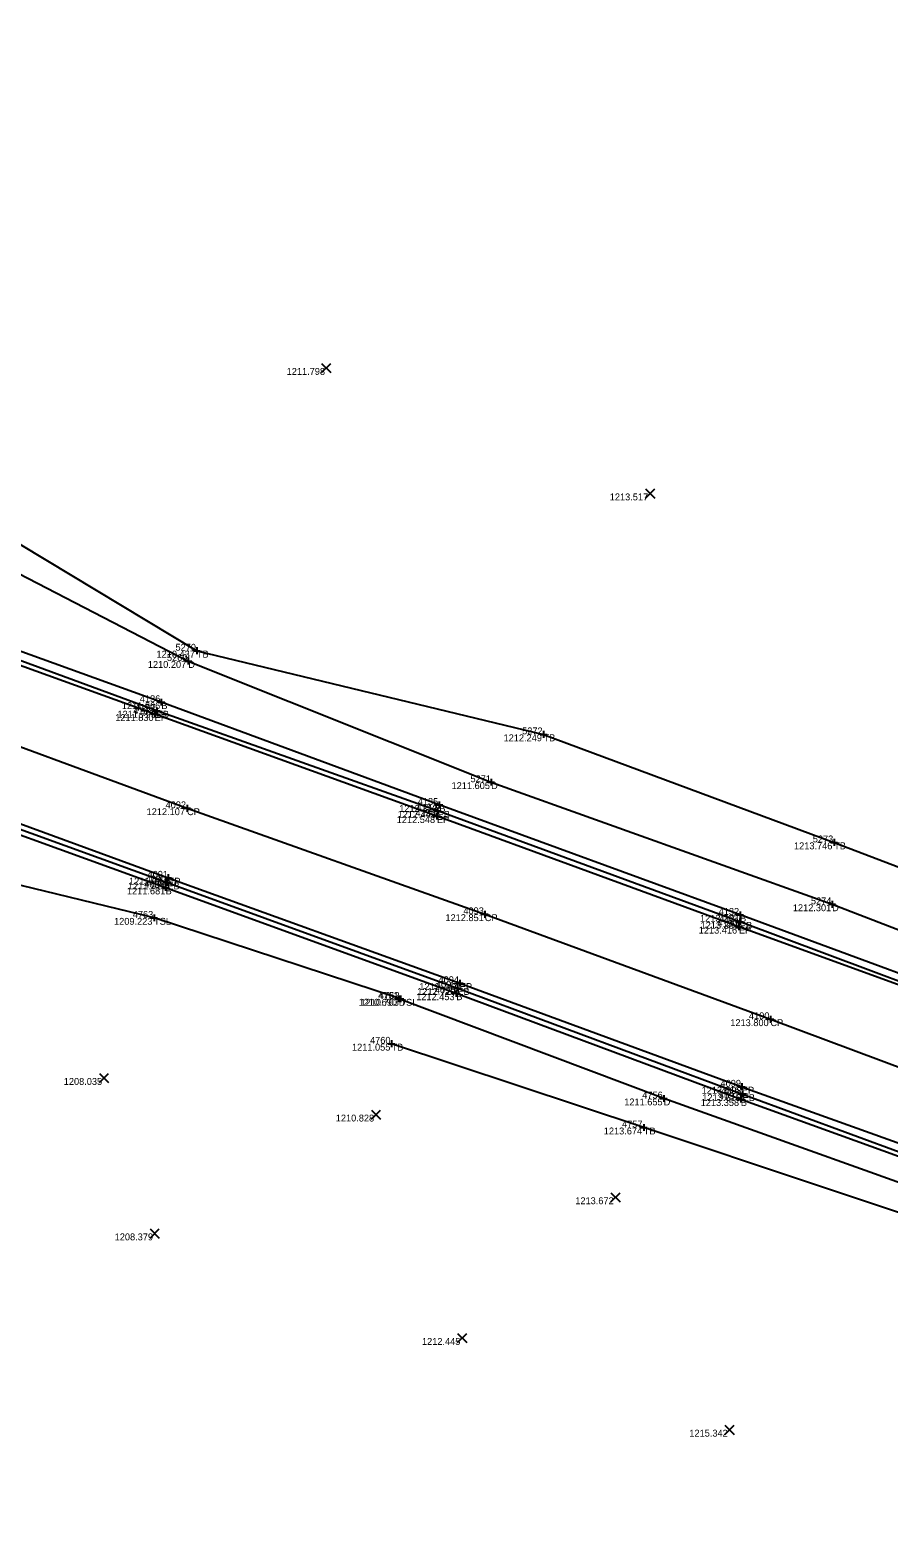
# Model space of a CAD drawing. Extents: x 2044996 to 2050343, y 455232 to 458054.
# Drawn here: x 2048351 to 2048475.8, y 456618.4 to 456837.6 of the extents above; entities that cross this region are included whole.
import ezdxf

# ---------------------------------------------------------------- set-up
doc = ezdxf.new("R2010")
doc.units = 0
for name, color, linetype in [('DR_X_Ditch', 7, 'Continuous'), ('DT_X_Contour_Minor', 7, 'Continuous'), ('DT_X_Contour_Text', 7, 'Continuous'), ('DT_X_Spot_Elev', 7, 'Continuous'), ('DT_X_Triangles', 7, 'Continuous'), ('DT_X_Void', 7, 'Continuous'), ('PV_X_COP', 7, 'Continuous'), ('PV_X_EOP', 7, 'Continuous'), ('PV_X_Shoulder_Aggregate', 7, 'Continuous'), ('SV_X_Break_Lines', 7, 'Continuous'), ('SV_X_Toe_of_Slope', 7, 'Continuous'), ('SV_X_Top_of_Bank', 7, 'Continuous')]:
    doc.layers.add(name, color=color, linetype=linetype)

msp = doc.modelspace()

# ---------------------------------------------------------------- linework, layer by layer
at = {"layer": 'DR_X_Ditch'}
for points in [[(2048335.55, 456765.74), (2048373.99, 456745.88), (2048418.01, 456728.27), (2048467.59, 456710.52), (2048510.97, 456693.84), (2048561.78, 456674.87), (2048608.72, 456657.51)], [(2048614.6, 456621.2), (2048574.15, 456636.27), (2048529.03, 456651.5), (2048491.62, 456664.97), (2048443.1, 456682.3), (2048404.59, 456696.79)]]:
    msp.add_lwpolyline(points, dxfattribs=at)
at = {"layer": 'DT_X_Spot_Elev'}
for p, q in [((2048393.36, 456787.8), (2048394.69, 456789.13)), ((2048393.36, 456789.13), (2048394.69, 456787.8)), ((2048440.47, 456769.56), (2048441.8, 456770.89)), ((2048440.47, 456770.89), (2048441.8, 456769.56)), ((2048361.07, 456684.62), (2048362.4, 456685.95)), ((2048361.07, 456685.95), (2048362.4, 456684.62)), ((2048400.6, 456679.29), (2048401.93, 456680.62)), ((2048400.6, 456680.62), (2048401.93, 456679.29)), ((2048435.42, 456667.27), (2048436.75, 456668.61)), ((2048435.42, 456668.61), (2048436.75, 456667.27)), ((2048368.44, 456662.02), (2048369.78, 456663.35)), ((2048368.44, 456663.35), (2048369.78, 456662.02)), ((2048413.14, 456646.83), (2048414.47, 456648.16)), ((2048413.14, 456648.16), (2048414.47, 456646.83)), ((2048451.99, 456633.49), (2048453.33, 456634.82)), ((2048451.99, 456634.82), (2048453.33, 456633.49))]:
    msp.add_line(p, q, dxfattribs=at)
at = {"layer": 'DT_X_Void'}
for p, q in [((2048375.24, 456747.88), (2048375.24, 456746.88)), ((2048373.49, 456745.88), (2048374.49, 456745.88)), ((2048373.99, 456746.38), (2048373.99, 456745.38)), ((2048373.99, 456745.88), (2048373.99, 456745.88)), ((2048374.74, 456747.38), (2048375.74, 456747.38)), ((2048375.24, 456747.38), (2048375.24, 456747.38)), ((2048369.4, 456739.15), (2048369.4, 456738.15)), ((2048369.57, 456739.9), (2048370.57, 456739.9)), ((2048370.07, 456740.4), (2048370.07, 456739.4)), ((2048370.07, 456739.9), (2048370.07, 456739.9)), ((2048368.61, 456738.16), (2048369.61, 456738.16)), ((2048368.9, 456738.65), (2048369.9, 456738.65)), ((2048369.11, 456738.66), (2048369.11, 456737.66)), ((2048369.11, 456738.16), (2048369.11, 456738.16)), ((2048369.4, 456738.65), (2048369.4, 456738.65)), ((2048425.14, 456735.22), (2048426.14, 456735.22)), ((2048425.64, 456735.72), (2048425.64, 456734.72)), ((2048425.64, 456735.22), (2048425.64, 456735.22)), ((2048417.51, 456728.27), (2048418.51, 456728.27)), ((2048418.01, 456728.77), (2048418.01, 456727.77)), ((2048418.01, 456728.27), (2048418.01, 456728.27)), ((2048373.31, 456724.48), (2048374.31, 456724.48)), ((2048373.81, 456724.98), (2048373.81, 456723.98)), ((2048373.81, 456724.48), (2048373.81, 456724.48)), ((2048409.74, 456724.1), (2048410.74, 456724.1)), ((2048409.98, 456724.96), (2048410.98, 456724.96)), ((2048410.13, 456723.84), (2048410.13, 456722.84)), ((2048410.24, 456724.6), (2048410.24, 456723.6)), ((2048410.24, 456724.1), (2048410.24, 456724.1)), ((2048410.48, 456725.46), (2048410.48, 456724.46)), ((2048410.48, 456724.96), (2048410.48, 456724.96)), ((2048409.63, 456723.34), (2048410.63, 456723.34)), ((2048410.13, 456723.34), (2048410.13, 456723.34)), ((2048467.38, 456719.52), (2048468.38, 456719.52)), ((2048467.88, 456720.02), (2048467.88, 456719.02)), ((2048467.88, 456719.52), (2048467.88, 456719.52)), ((2048371.07, 456714.88), (2048371.07, 456713.88)), ((2048370.19, 456712.96), (2048371.19, 456712.96)), ((2048370.44, 456713.7), (2048371.44, 456713.7)), ((2048370.57, 456714.38), (2048371.57, 456714.38)), ((2048370.69, 456713.46), (2048370.69, 456712.46)), ((2048370.69, 456712.96), (2048370.69, 456712.96)), ((2048370.94, 456714.2), (2048370.94, 456713.2)), ((2048370.94, 456713.7), (2048370.94, 456713.7)), ((2048371.07, 456714.38), (2048371.07, 456714.38)), ((2048467.09, 456710.52), (2048468.09, 456710.52)), ((2048467.59, 456711.02), (2048467.59, 456710.02)), ((2048467.59, 456710.52), (2048467.59, 456710.52)), ((2048368.52, 456708.55), (2048369.52, 456708.55)), ((2048369.02, 456709.05), (2048369.02, 456708.05)), ((2048369.02, 456708.55), (2048369.02, 456708.55)), ((2048416.59, 456709.08), (2048417.59, 456709.08)), ((2048417.09, 456709.58), (2048417.09, 456708.58)), ((2048417.09, 456709.08), (2048417.09, 456709.08)), ((2048453.7, 456708.99), (2048454.7, 456708.99)), ((2048454.17, 456708.47), (2048454.17, 456707.47)), ((2048454.2, 456709.49), (2048454.2, 456708.49)), ((2048454.2, 456708.99), (2048454.2, 456708.99)), ((2048453.53, 456707.27), (2048454.53, 456707.27)), ((2048453.67, 456707.97), (2048454.67, 456707.97)), ((2048454.03, 456707.77), (2048454.03, 456706.77)), ((2048454.03, 456707.27), (2048454.03, 456707.27)), ((2048454.17, 456707.97), (2048454.17, 456707.97)), ((2048413.46, 456699.57), (2048413.46, 456698.57)), ((2048404.59, 456697.29), (2048404.59, 456696.29)), ((2048404.84, 456697.28), (2048404.84, 456696.28)), ((2048412.45, 456697.59), (2048413.45, 456697.59)), ((2048412.61, 456698.36), (2048413.61, 456698.36)), ((2048412.95, 456698.09), (2048412.95, 456697.09)), ((2048412.95, 456697.59), (2048412.95, 456697.59)), ((2048412.96, 456699.07), (2048413.96, 456699.07)), ((2048413.11, 456698.86), (2048413.11, 456697.86)), ((2048413.11, 456698.36), (2048413.11, 456698.36)), ((2048413.46, 456699.07), (2048413.46, 456699.07)), ((2048404.09, 456696.79), (2048405.09, 456696.79)), ((2048404.34, 456696.78), (2048405.34, 456696.78)), ((2048404.59, 456696.79), (2048404.59, 456696.79)), ((2048404.84, 456696.78), (2048404.84, 456696.78)), ((2048458.11, 456693.82), (2048459.11, 456693.82)), ((2048458.61, 456694.32), (2048458.61, 456693.32)), ((2048458.61, 456693.82), (2048458.61, 456693.82)), ((2048403.53, 456690.76), (2048403.53, 456689.76)), ((2048403.03, 456690.26), (2048404.03, 456690.26)), ((2048403.53, 456690.26), (2048403.53, 456690.26)), ((2048453.96, 456684.01), (2048454.96, 456684.01)), ((2048454.46, 456684.51), (2048454.46, 456683.51)), ((2048454.46, 456684.01), (2048454.46, 456684.01)), ((2048442.6, 456682.3), (2048443.6, 456682.3)), ((2048443.1, 456682.8), (2048443.1, 456681.8)), ((2048443.1, 456682.3), (2048443.1, 456682.3)), ((2048453.81, 456682.22), (2048454.81, 456682.22)), ((2048454.07, 456682.93), (2048455.07, 456682.93)), ((2048454.31, 456682.72), (2048454.31, 456681.72)), ((2048454.31, 456682.22), (2048454.31, 456682.22)), ((2048454.57, 456683.43), (2048454.57, 456682.43)), ((2048454.57, 456682.93), (2048454.57, 456682.93)), ((2048439.7, 456678.08), (2048440.7, 456678.08)), ((2048440.2, 456678.58), (2048440.2, 456677.58)), ((2048440.2, 456678.08), (2048440.2, 456678.08))]:
    msp.add_line(p, q, dxfattribs=at)
at = {"layer": 'PV_X_COP'}
msp.add_lwpolyline([(2047721.58, 456961.45), (2047764.11, 456945.53), (2047805.42, 456930.56), (2047848.07, 456915.19), (2047886.38, 456901.23), (2047928.53, 456886.16), (2047967.24, 456872.35), (2048004.2, 456859.18), (2048043.3, 456845.25), (2048086.02, 456829.64), (2048125.99, 456815.39), (2048168.62, 456799.78), (2048207.67, 456785.38), (2048251.12, 456769.74), (2048292.61, 456754.36), (2048333.81, 456739.22), (2048373.81, 456724.48), (2048417.09, 456709.08), (2048458.61, 456693.82), (2048498.86, 456678.79), (2048537.43, 456664.8), (2048579.13, 456649.5), (2048615.78, 456636.27)], dxfattribs=at)
at = {"layer": 'PV_X_EOP'}
for p, q in [((2048369.11, 456738.16), (2048329.3, 456752.57)), ((2048410.13, 456723.34), (2048369.11, 456738.16)), ((2048331.67, 456728.74), (2048371.07, 456714.38)), ((2048454.03, 456707.27), (2048410.13, 456723.34)), ((2048371.07, 456714.38), (2048413.46, 456699.07)), ((2048498.14, 456691.21), (2048454.03, 456707.27)), ((2048413.46, 456699.07), (2048454.46, 456684.01)), ((2048454.46, 456684.01), (2048494.49, 456669.66))]:
    msp.add_line(p, q, dxfattribs=at)
at = {"layer": 'PV_X_Shoulder_Aggregate'}
for points in [[(2048620.54, 456647.12), (2048583.12, 456660.67), (2048539.73, 456676.45), (2048498.23, 456691.52), (2048454.17, 456707.97), (2048410.24, 456724.1), (2048369.4, 456738.65), (2048329.21, 456753.43), (2048288.45, 456768.21), (2048244.06, 456784.69), (2048200.54, 456800.78), (2048154.81, 456817.47), (2048112.55, 456832.71), (2048067.31, 456849.18), (2048026.51, 456863.76), (2047982.25, 456879.67), (2047938.09, 456895.41), (2047894.6, 456910.89), (2047855.83, 456924.74), (2047813.34, 456939.9), (2047765.41, 456957.6), (2047718.77, 456974.89)], [(2048040.39, 456833.65), (2048080.57, 456819.36), (2048122.88, 456804.21), (2048163.75, 456789.21), (2048203.9, 456774.44), (2048245.67, 456759.42), (2048288.72, 456743.61), (2048331.35, 456728.01), (2048370.94, 456713.7), (2048413.11, 456698.36), (2048454.57, 456682.93), (2048494.04, 456668.41), (2048534.01, 456653.96), (2048574.84, 456639.09), (2048611.82, 456625.41)]]:
    msp.add_lwpolyline(points, dxfattribs=at)
at = {"layer": 'SV_X_Break_Lines'}
for points in [[(2048620.73, 456648.35), (2048583.39, 456661.98), (2048539.9, 456677.65), (2048498.37, 456692.73), (2048454.2, 456708.99), (2048410.48, 456724.96), (2048370.07, 456739.9), (2048329.65, 456754.5), (2048288.87, 456769.18), (2048244.36, 456785.65), (2048200.73, 456801.81), (2048154.72, 456818.61), (2048112.67, 456833.97), (2048067.63, 456850.21), (2048026.62, 456865.12), (2047982.64, 456881.49), (2047938.6, 456897.69), (2047895.04, 456913.55), (2047856.96, 456927.13), (2047813.61, 456942.44), (2047766.63, 456959.74), (2047718.99, 456976.33)], [(2047983.65, 456851.86), (2047998.98, 456847.09), (2048040.01, 456832.79), (2048080.02, 456818.41), (2048122.45, 456803.47), (2048163.47, 456788.33), (2048203.54, 456773.63), (2048245.32, 456758.55), (2048288.48, 456742.77), (2048331.35, 456727.2), (2048370.69, 456712.96), (2048412.95, 456697.59), (2048454.31, 456682.22), (2048493.85, 456667.9), (2048533.48, 456653.1), (2048574.57, 456638.27), (2048611.5, 456624.45)]]:
    msp.add_lwpolyline(points, dxfattribs=at)
at = {"layer": 'SV_X_Toe_of_Slope'}
msp.add_lwpolyline([(2048404.84, 456696.78), (2048369.02, 456708.55), (2048337.28, 456716.27), (2048320.26, 456716.03)], dxfattribs=at)
at = {"layer": 'SV_X_Top_of_Bank'}
for points in [[(2048339.12, 456780.89), (2048338.6, 456769.39), (2048375.24, 456747.38), (2048425.64, 456735.22), (2048467.88, 456719.52), (2048517.9, 456700.47), (2048561.92, 456683.71), (2048612.49, 456664.63)], [(2048613.95, 456618.45), (2048573.55, 456632.08), (2048525.05, 456647.34), (2048490.68, 456661.21), (2048440.2, 456678.08), (2048403.53, 456690.26)]]:
    msp.add_lwpolyline(points, dxfattribs=at)

# ---------------------------------------------------------------- texts
at = {"layer": 'DT_X_Contour_Minor'}
for s, p in [('1211.798', (2048388.29, 456787.47)), ('1213.517', (2048435.26, 456769.23)), ('1210.207', (2048368.11, 456744.88)), ('1210.437', (2048369.37, 456746.38)), ('1211.666', (2048364.33, 456738.9)), ('1211.830', (2048363.37, 456737.16)), ('1211.799', (2048363.69, 456737.65)), ('1212.249', (2048419.82, 456734.22)), ('1211.605', (2048412.26, 456727.27)), ('1212.107', (2048367.93, 456723.48)), ('1212.443', (2048404.42, 456723.1)), ('1212.313', (2048404.65, 456723.96)), ('1212.548', (2048404.29, 456722.34)), ('1213.746', (2048462.04, 456718.52)), ('1211.681', (2048365.07, 456711.96)), ('1211.919', (2048365.23, 456712.7)), ('1211.984', (2048365.37, 456713.38)), ('1212.301', (2048461.87, 456709.52)), ('1209.223', (2048363.2, 456707.55)), ('1212.851', (2048411.37, 456708.08)), ('1213.283', (2048448.38, 456707.99)), ('1213.416', (2048448.19, 456706.27)), ('1213.391', (2048448.46, 456706.97)), ('1212.453', (2048407.12, 456696.59)), ('1212.720', (2048407.27, 456697.36)), ('1212.747', (2048407.58, 456698.07)), ('1210.690', (2048398.75, 456695.79)), ('1210.703', (2048399.02, 456695.78)), ('1213.800', (2048452.78, 456692.82)), ('1211.055', (2048397.79, 456689.26)), ('1208.035', (2048355.89, 456684.28)), ('1213.615', (2048448.61, 456683.01)), ('1211.655', (2048437.36, 456681.3)), ('1213.358', (2048448.48, 456681.22)), ('1213.615', (2048448.72, 456681.93)), ('1210.828', (2048395.43, 456678.96)), ('1213.674', (2048434.39, 456677.08)), ('1213.672', (2048430.25, 456666.94)), ('1208.379', (2048363.29, 456661.69)), ('1212.445', (2048407.96, 456646.49)), ('1215.342', (2048446.83, 456633.16))]:
    msp.add_text(s, height=1, dxfattribs=at).set_placement(p)
at = {"layer": 'DT_X_Contour_Text'}
for s, p in [('D', (2048373.99, 456744.88)), ('TB', (2048375.24, 456746.38)), ('B', (2048370.07, 456738.9)), ('EP', (2048369.11, 456737.16)), ('EB', (2048369.4, 456737.65)), ('TB', (2048425.64, 456734.22)), ('D', (2048418.01, 456727.27)), ('CP', (2048373.81, 456723.48)), ('EB', (2048410.24, 456723.1)), ('B', (2048410.48, 456723.96)), ('EP', (2048410.13, 456722.34)), ('TB', (2048467.88, 456718.52)), ('B', (2048370.69, 456711.96)), ('EB', (2048370.94, 456712.7)), ('EP', (2048371.07, 456713.38)), ('D', (2048467.59, 456709.52)), ('TSL', (2048369.02, 456707.55)), ('CP', (2048417.09, 456708.08)), ('B', (2048454.2, 456707.99)), ('EP', (2048454.03, 456706.27)), ('EB', (2048454.17, 456706.97)), ('B', (2048412.95, 456696.59)), ('EB', (2048413.11, 456697.36)), ('EP', (2048413.46, 456698.07)), ('D', (2048404.59, 456695.79)), ('TSL', (2048404.84, 456695.78)), ('CP', (2048458.61, 456692.82)), ('TB', (2048403.53, 456689.26)), ('EP', (2048454.46, 456683.01)), ('D', (2048443.1, 456681.3)), ('B', (2048454.31, 456681.22)), ('EB', (2048454.57, 456681.93)), ('TB', (2048440.2, 456677.08))]:
    msp.add_text(s, height=1, dxfattribs=at).set_placement(p)
at = {"layer": 'DT_X_Triangles'}
for s, p in [('5270', (2048372.13, 456747.38)), ('5269', (2048370.89, 456745.88)), ('4138', (2048365.99, 456738.16)), ('4137', (2048366.24, 456738.65)), ('4136', (2048366.95, 456739.9)), ('5272', (2048422.52, 456735.22)), ('5271', (2048415.01, 456728.27)), ('4135', (2048407.35, 456724.96)), ('4092', (2048370.69, 456724.48)), ('4133', (2048407.02, 456723.34)), ('4134', (2048407.15, 456724.1)), ('5273', (2048464.77, 456719.52)), ('4090', (2048367.82, 456713.7)), ('4091', (2048368.07, 456714.38)), ('4089', (2048367.59, 456712.96)), ('5274', (2048464.5, 456710.52)), ('4763', (2048365.92, 456708.55)), ('4093', (2048413.98, 456709.08)), ('4130', (2048450.91, 456707.27)), ('4132', (2048451.09, 456708.99)), ('4131', (2048451.18, 456707.97)), ('4095', (2048409.98, 456698.36)), ('4094', (2048410.37, 456699.07)), ('4761', (2048401.59, 456696.79)), ('4762', (2048401.73, 456696.78)), ('4096', (2048409.83, 456697.59)), ('4100', (2048455.49, 456693.82)), ('4760', (2048400.41, 456690.26)), ('4099', (2048451.36, 456684.01)), ('4756', (2048439.98, 456682.3)), ('4097', (2048451.15, 456682.22)), ('4098', (2048451.45, 456682.93)), ('4757', (2048437.04, 456678.08))]:
    msp.add_text(s, height=1, dxfattribs=at).set_placement(p)

doc.saveas('drawing.dxf')
